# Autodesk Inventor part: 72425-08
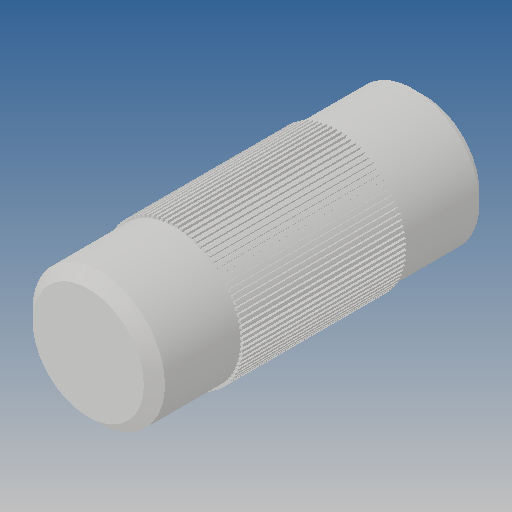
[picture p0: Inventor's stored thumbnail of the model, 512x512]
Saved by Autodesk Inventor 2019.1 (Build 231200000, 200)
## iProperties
Created: 2012-10
Part Number: 72425-08
Material: Ogólny
Document SubType Name: Modeling
Designer: CADENGINEERING4
Density: 1 g/cm^3
Appearance: Domyślna
Author: CADENGINEERING4
Revision Number: ÈÎºÎ
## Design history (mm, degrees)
feature "ÊäÈë1"
node "Bryła1"
